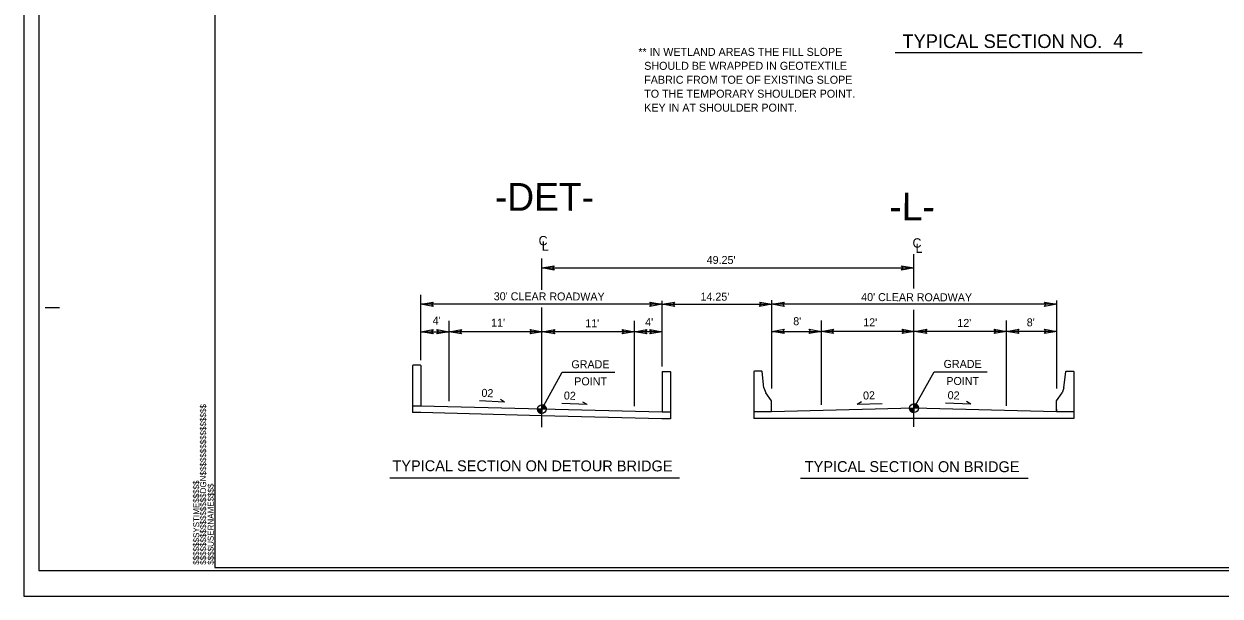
# Model space of a CAD drawing. Extents: x 1497225 to 1499181, y 579958 to 582278.
# Drawn here: x 1497225 to 1498271, y 579958 to 580459 of the extents above; entities that cross this region are included whole.
import ezdxf

# ---------------------------------------------------------------- set-up
doc = ezdxf.new("R2010")
doc.units = 0
for name, color, linetype in [('Old_Level_1', 7, 'Continuous'), ('Old_Level_11', 7, 'Continuous'), ('Old_Level_2', 7, 'Continuous'), ('Old_Level_3', 7, 'Continuous'), ('Prop Dimension Text', 7, 'Continuous'), ('Sheet Cutting Line CELL', 7, 'Continuous'), ('Sheet Plot Border Inside CELL', 7, 'Continuous'), ('Sheet Plot Border Outside CELL', 7, 'Continuous'), ('Sheet Typical CELL', 7, 'Continuous'), ('Typical Text Label CELL', 7, 'Continuous')]:
    doc.layers.add(name, color=color, linetype=linetype)

msp = doc.modelspace()

# ---------------------------------------------------------------- linework, layer by layer
at = {"layer": 'Old_Level_1'}
for p, q in [((1497678.2, 580226), (1497678.2, 580253.2)), ((1498003.6, 580227), (1498003.6, 580257.2)), ((1497678.2, 580245.1), (1498003.6, 580245.1)), ((1497572.3, 580164.3), (1497572.3, 580221.6)), ((1497879.4, 580139.6), (1497879.4, 580216.9)), ((1498128.4, 580139.6), (1498128.4, 580216.5)), ((1497783.5, 580213.3), (1497572.3, 580213.3)), ((1497678.2, 580105.7), (1497678.2, 580210.4)), ((1497783.5, 580158.9), (1497783.5, 580216.2)), ((1497783.5, 580213.3), (1497879.4, 580213.3)), ((1498128.4, 580213.3), (1497879.4, 580213.3)), ((1498003.6, 580106), (1498003.6, 580208.5)), ((1497597.2, 580128.4), (1497597.2, 580198.9)), ((1497759.2, 580124.1), (1497759.2, 580198.9)), ((1497922.6, 580125.2), (1497922.6, 580199.2)), ((1498084.6, 580124.4), (1498084.6, 580199.2)), ((1497572.3, 580189.3), (1497597.2, 580189.3)), ((1497678.7, 580189.3), (1497597.2, 580189.3)), ((1497759.2, 580189.3), (1497678.7, 580189.3)), ((1497783.5, 580189.3), (1497759.2, 580189.3)), ((1497879.4, 580189.6), (1497922.6, 580189.6)), ((1498004.1, 580189.6), (1497922.6, 580189.6)), ((1498084.6, 580189.6), (1498004.1, 580189.6)), ((1498128.4, 580189.6), (1498084.6, 580189.6)), ((1497565.5, 580159.9), (1497565.1, 580159.6)), ((1497565.1, 580159.6), (1497565.1, 580118.5)), ((1497572, 580159.9), (1497565.5, 580159.9)), ((1497572.3, 580159.6), (1497572, 580159.9)), ((1497572.3, 580159.6), (1497572.3, 580124.3)), ((1497678.2, 580121.6), (1497695.9, 580153.9)), ((1497695.9, 580153.9), (1497742, 580153.9)), ((1497783.5, 580154.2), (1497783.8, 580154.5)), ((1497783.5, 580154.2), (1497783.5, 580118.9)), ((1497783.8, 580154.5), (1497790.3, 580154.5)), ((1497790.3, 580154.5), (1497790.7, 580154.2)), ((1497790.7, 580154.2), (1497790.7, 580113.1)), ((1497864, 580154.8), (1497863.6, 580154.4)), ((1497863.6, 580154.4), (1497863.6, 580113.3)), ((1497870.5, 580154.8), (1497864, 580154.8)), ((1497870.9, 580154.4), (1497870.5, 580154.8)), ((1497872.4, 580140.1), (1497870.9, 580154.4)), ((1498003.6, 580122.4), (1498021.3, 580154.2)), ((1498021.3, 580154.2), (1498067.5, 580154.2)), ((1498134.7, 580140.1), (1498136.3, 580154.4)), ((1498136.3, 580154.4), (1498136.6, 580154.8)), ((1498136.6, 580154.8), (1498143.1, 580154.8)), ((1498143.1, 580154.8), (1498143.5, 580154.4)), ((1498143.5, 580154.4), (1498143.5, 580113.3)), ((1497872.4, 580140.1), (1497873.9, 580135.9)), ((1497878.9, 580128.9), (1497873.9, 580135.9)), ((1498128.3, 580128.9), (1498133.2, 580135.9)), ((1498134.7, 580140.1), (1498133.2, 580135.9)), ((1497572.3, 580124.3), (1497565.1, 580124.3)), ((1497678.2, 580121.6), (1497572.3, 580124.3)), ((1497678.2, 580121.6), (1497678.2, 580125.5)), ((1497878.9, 580119.2), (1497878.9, 580128.9)), ((1498003.6, 580122.4), (1497878.9, 580119.2)), ((1497999.8, 580122.4), (1498003.6, 580122.4)), ((1498003.6, 580122.4), (1498003.6, 580126.2)), ((1498007.4, 580122.4), (1498003.6, 580122.4)), ((1498003.6, 580118.6), (1498003.6, 580122.4)), ((1498003.6, 580122.4), (1498003.6, 580118.6)), ((1498128.3, 580119.2), (1498003.6, 580122.4)), ((1498128.3, 580119.2), (1498128.3, 580128.9)), ((1497572.2, 580118.5), (1497565.1, 580118.5)), ((1497678, 580115.8), (1497572.2, 580118.5)), ((1497674.4, 580121.6), (1497678.2, 580121.6)), ((1497783.2, 580113.1), (1497678, 580115.8)), ((1497682, 580121.6), (1497678.2, 580121.6)), ((1497678.2, 580117.8), (1497678.2, 580121.6)), ((1497678.2, 580121.6), (1497678.2, 580117.8)), ((1497783.4, 580118.9), (1497678.2, 580121.6)), ((1497790.7, 580118.9), (1497783.4, 580118.9)), ((1497790.7, 580113.1), (1497783.4, 580113.1)), ((1497878.9, 580119.2), (1497863.6, 580119.2)), ((1498003.6, 580113.3), (1497863.6, 580113.3)), ((1498143.5, 580113.3), (1498003.6, 580113.3)), ((1498128.3, 580121.5), (1498128.3, 580119.2)), ((1498143.5, 580119.2), (1498128.3, 580119.2)), ((1497545.2, 580061.4), (1497798.5, 580061.4)), ((1497904.5, 580061.3), (1498103.6, 580061.3))]:
    msp.add_line(p, q, dxfattribs=at)
for points in [[(1497678.2, 580125.5), (1497678.2, 580125.5), (1497678.2, 580121.6)], [(1497678.2, 580125.5), (1497678.2, 580121.6)], [(1497678.3, 580125.5), (1497678.3, 580121.6)], [(1497678.4, 580125.5), (1497678.4, 580121.6)], [(1497678.5, 580125.4), (1497678.5, 580121.6)], [(1497678.6, 580125.4), (1497678.6, 580121.6)], [(1497678.7, 580125.4), (1497678.7, 580121.6)], [(1497678.8, 580125.4), (1497678.8, 580121.6)], [(1497678.8, 580125.4), (1497678.8, 580121.6)], [(1497678.9, 580125.4), (1497678.9, 580121.6)], [(1497678.9, 580125.4), (1497678.9, 580121.6)], [(1497679, 580125.3), (1497679, 580121.6)], [(1497679.1, 580125.3), (1497679.1, 580121.6)], [(1497679.2, 580125.3), (1497679.2, 580121.6)], [(1497679.3, 580125.3), (1497679.3, 580121.6)], [(1497679.4, 580125.2), (1497679.4, 580121.6)], [(1497679.4, 580125.2), (1497679.4, 580121.6)], [(1497679.5, 580125.2), (1497679.5, 580121.6)], [(1497679.6, 580125.2), (1497679.6, 580121.6)], [(1497679.6, 580125.1), (1497679.6, 580121.6)], [(1497679.7, 580125.1), (1497679.7, 580121.6)], [(1497679.8, 580125), (1497679.8, 580121.6)], [(1497679.9, 580125), (1497679.9, 580121.6)], [(1497680, 580124.9), (1497680, 580121.6)], [(1497680, 580124.9), (1497680, 580121.6)], [(1497680.1, 580124.9), (1497680.1, 580121.6)], [(1497680.2, 580124.9), (1497680.2, 580121.6)], [(1497680.3, 580124.8), (1497680.3, 580121.6)], [(1497680.3, 580124.8), (1497680.3, 580121.6)], [(1497680.4, 580124.7), (1497680.4, 580121.6)], [(1497680.5, 580124.6), (1497680.5, 580121.6)], [(1497680.6, 580124.6), (1497680.6, 580121.6)], [(1497680.6, 580124.5), (1497680.6, 580121.6)], [(1497680.7, 580124.4), (1497680.7, 580121.6)], [(1497680.8, 580124.3), (1497680.8, 580121.6)], [(1497680.9, 580124.3), (1497680.9, 580121.6)], [(1497681, 580124.3), (1497681, 580121.6)], [(1497681, 580124.2), (1497681, 580121.6)], [(1497681.1, 580124.1), (1497681.1, 580121.6)], [(1497681.2, 580123.9), (1497681.2, 580121.6)], [(1497681.2, 580123.8), (1497681.2, 580121.6)], [(1497681.3, 580123.7), (1497681.3, 580121.6)], [(1497681.4, 580123.7), (1497681.4, 580121.6)], [(1497681.5, 580123.5), (1497681.5, 580121.6)], [(1497681.6, 580123.3), (1497681.6, 580121.6)], [(1497681.7, 580123.2), (1497681.7, 580121.6)], [(1497681.7, 580123.1), (1497681.7, 580121.6)], [(1497681.8, 580122.8), (1497681.8, 580121.6)], [(1497681.8, 580122.5), (1497681.8, 580121.6)], [(1497999.8, 580122.4), (1497999.8, 580121.9)], [(1497999.9, 580122.4), (1497999.9, 580121.5)], [(1498000, 580122.4), (1498000, 580121.3)], [(1498000, 580122.4), (1498000, 580121)], [(1498000, 580122.4), (1498000, 580120.8)], [(1498000.1, 580122.4), (1498000.1, 580120.7)], [(1498000.2, 580122.4), (1498000.2, 580120.6)], [(1498000.3, 580122.4), (1498000.3, 580120.4)], [(1498000.4, 580122.4), (1498000.4, 580120.3)], [(1498000.5, 580122.4), (1498000.5, 580120.1)], [(1498000.6, 580122.4), (1498000.6, 580120.1)], [(1498000.6, 580122.4), (1498000.6, 580120)], [(1498000.7, 580122.4), (1498000.7, 580119.9)], [(1498000.7, 580122.4), (1498000.7, 580119.8)], [(1498000.8, 580122.4), (1498000.8, 580119.7)], [(1498000.9, 580122.4), (1498000.9, 580119.6)], [(1498001, 580122.4), (1498001, 580119.5)], [(1498001.1, 580122.4), (1498001.1, 580119.4)], [(1498001.2, 580122.4), (1498001.2, 580119.5)], [(1498001.2, 580122.4), (1498001.2, 580119.4)], [(1498001.3, 580122.4), (1498001.3, 580119.3)], [(1498001.4, 580122.4), (1498001.4, 580119.3)], [(1498001.4, 580122.4), (1498001.4, 580119.2)], [(1498001.5, 580122.4), (1498001.5, 580119.2)], [(1498001.6, 580122.4), (1498001.6, 580119.1)], [(1498001.7, 580122.4), (1498001.7, 580119)], [(1498001.8, 580122.4), (1498001.8, 580119)], [(1498001.8, 580122.4), (1498001.8, 580118.9)], [(1498001.9, 580122.4), (1498001.9, 580118.9)], [(1498002, 580122.4), (1498002, 580118.9)], [(1498002.1, 580122.4), (1498002.1, 580118.9)], [(1498002.1, 580122.4), (1498002.1, 580118.9)], [(1498002.2, 580122.4), (1498002.2, 580118.9)], [(1498002.3, 580122.4), (1498002.3, 580118.8)], [(1498002.4, 580122.4), (1498002.4, 580118.8)], [(1498002.4, 580122.4), (1498002.4, 580118.8)], [(1498002.5, 580122.4), (1498002.5, 580118.7)], [(1498002.6, 580122.4), (1498002.6, 580118.7)], [(1498002.7, 580122.4), (1498002.7, 580118.7)], [(1498002.8, 580122.4), (1498002.8, 580118.7)], [(1498002.8, 580122.4), (1498002.8, 580118.6)], [(1498002.9, 580122.4), (1498002.9, 580118.6)], [(1498003, 580122.4), (1498003, 580118.6)], [(1498003, 580122.4), (1498003, 580118.6)], [(1498003.1, 580122.4), (1498003.1, 580118.6)], [(1498003.2, 580122.4), (1498003.2, 580118.6)], [(1498003.3, 580122.4), (1498003.3, 580118.6)], [(1498003.4, 580122.4), (1498003.4, 580118.6)], [(1498003.5, 580122.4), (1498003.5, 580118.6)], [(1498003.5, 580122.4), (1498003.5, 580118.6), (1498003.5, 580118.6)], [(1498003.6, 580126.2), (1498003.6, 580126.2), (1498003.7, 580122.4)], [(1498003.6, 580126.2), (1498003.7, 580122.4)], [(1498003.7, 580126.2), (1498003.7, 580122.4)], [(1498003.8, 580126.2), (1498003.8, 580122.4)], [(1498003.9, 580126.1), (1498003.9, 580122.4)], [(1498004, 580126.1), (1498004, 580122.4)], [(1498004.1, 580126.1), (1498004.1, 580122.4)], [(1498004.2, 580126.1), (1498004.2, 580122.4)], [(1498004.3, 580126.1), (1498004.3, 580122.4)], [(1498004.3, 580126.1), (1498004.3, 580122.4)], [(1498004.3, 580126.1), (1498004.3, 580122.4)], [(1498004.4, 580126.1), (1498004.4, 580122.4)], [(1498004.5, 580126.1), (1498004.5, 580122.4)], [(1498004.6, 580126.1), (1498004.6, 580122.4)], [(1498004.7, 580126.1), (1498004.7, 580122.4)], [(1498004.8, 580126), (1498004.8, 580122.4)], [(1498004.9, 580126), (1498004.8, 580122.4)], [(1498004.9, 580126), (1498004.9, 580122.4)], [(1498005, 580126), (1498005, 580122.4)], [(1498005, 580125.9), (1498005, 580122.4)], [(1498005.1, 580125.9), (1498005.1, 580122.4)], [(1498005.2, 580125.8), (1498005.2, 580122.4)], [(1498005.3, 580125.8), (1498005.3, 580122.4)], [(1498005.4, 580125.7), (1498005.4, 580122.4)], [(1498005.5, 580125.7), (1498005.5, 580122.4)], [(1498005.5, 580125.6), (1498005.5, 580122.4)], [(1498005.6, 580125.6), (1498005.6, 580122.4)], [(1498005.7, 580125.5), (1498005.7, 580122.4)], [(1498005.7, 580125.5), (1498005.7, 580122.4)], [(1498005.8, 580125.5), (1498005.8, 580122.4)], [(1498005.9, 580125.4), (1498005.9, 580122.4)], [(1498006, 580125.4), (1498006, 580122.4)], [(1498006.1, 580125.3), (1498006.1, 580122.4)], [(1498006.1, 580125.2), (1498006.1, 580122.4)], [(1498006.2, 580125.1), (1498006.2, 580122.4)], [(1498006.3, 580125), (1498006.3, 580122.4)], [(1498006.4, 580125), (1498006.4, 580122.4)], [(1498006.4, 580124.9), (1498006.4, 580122.4)], [(1498006.5, 580124.9), (1498006.5, 580122.4)], [(1498006.6, 580124.7), (1498006.6, 580122.4)], [(1498006.7, 580124.6), (1498006.7, 580122.4)], [(1498006.7, 580124.5), (1498006.7, 580122.4)], [(1498006.8, 580124.4), (1498006.8, 580122.4)], [(1498006.9, 580124.3), (1498006.9, 580122.4)], [(1498007, 580124.1), (1498007, 580122.4)], [(1498007.1, 580124), (1498007.1, 580122.4)], [(1498007.1, 580123.8), (1498007.1, 580122.4)], [(1498007.2, 580123.6), (1498007.2, 580122.4)], [(1498007.3, 580123.3), (1498007.3, 580122.4)], [(1498007.3, 580122.9), (1498007.3, 580122.4)], [(1497674.4, 580121.6), (1497674.4, 580121.2)], [(1497674.5, 580121.6), (1497674.5, 580120.7)], [(1497674.5, 580121.6), (1497674.5, 580120.2)], [(1497674.5, 580121.6), (1497674.5, 580120.5)], [(1497674.6, 580121.6), (1497674.6, 580120.1)], [(1497674.7, 580121.6), (1497674.7, 580119.9)], [(1497674.8, 580121.6), (1497674.8, 580119.8)], [(1497674.9, 580121.6), (1497674.9, 580119.6)], [(1497675, 580121.6), (1497675, 580119.5)], [(1497675.1, 580121.6), (1497675.1, 580119.4)], [(1497675.2, 580121.6), (1497675.2, 580119.3)], [(1497675.2, 580121.6), (1497675.2, 580119.2)], [(1497675.3, 580121.6), (1497675.3, 580119.1)], [(1497675.3, 580121.6), (1497675.3, 580119)], [(1497675.4, 580121.6), (1497675.4, 580118.9)], [(1497675.5, 580121.6), (1497675.5, 580118.9)], [(1497675.6, 580121.6), (1497675.6, 580118.8)], [(1497675.7, 580121.6), (1497675.7, 580118.7)], [(1497675.8, 580121.6), (1497675.8, 580118.7)], [(1497675.8, 580121.6), (1497675.8, 580118.6)], [(1497675.9, 580121.6), (1497675.9, 580118.5)], [(1497676, 580121.6), (1497676, 580118.5)], [(1497676, 580121.6), (1497676, 580118.4)], [(1497676.1, 580121.6), (1497676.1, 580118.4)], [(1497676.2, 580121.6), (1497676.2, 580118.3)], [(1497676.3, 580121.6), (1497676.3, 580118.3)], [(1497676.4, 580121.6), (1497676.4, 580118.3)], [(1497676.4, 580121.6), (1497676.4, 580118.2)], [(1497676.5, 580121.6), (1497676.5, 580118.2)], [(1497676.6, 580121.6), (1497676.6, 580118.2)], [(1497676.7, 580121.6), (1497676.7, 580118.1)], [(1497676.7, 580121.6), (1497676.7, 580118.1)], [(1497676.8, 580121.6), (1497676.8, 580118.1)], [(1497676.9, 580121.6), (1497676.9, 580118)], [(1497677, 580121.6), (1497677, 580118)], [(1497677, 580121.6), (1497677, 580118)], [(1497677.1, 580121.6), (1497677.1, 580117.9)], [(1497677.2, 580121.6), (1497677.2, 580117.9)], [(1497677.3, 580121.6), (1497677.3, 580117.9)], [(1497677.4, 580121.6), (1497677.4, 580117.9)], [(1497677.4, 580121.6), (1497677.4, 580117.8)], [(1497677.5, 580121.6), (1497677.5, 580117.8)], [(1497677.6, 580121.6), (1497677.6, 580117.8)], [(1497677.6, 580121.6), (1497677.6, 580117.8)], [(1497677.7, 580121.6), (1497677.7, 580117.8)], [(1497677.8, 580121.6), (1497677.8, 580117.8)], [(1497677.9, 580121.6), (1497677.9, 580117.8)], [(1497678, 580121.6), (1497678, 580117.8)], [(1497678.1, 580121.6), (1497678.1, 580117.8)], [(1497678.1, 580121.6), (1497678.1, 580117.8), (1497678.1, 580117.8)], [(1497681.9, 580122.1), (1497681.9, 580121.6)]]:
    msp.add_lwpolyline(points, dxfattribs=at)
for centre in [(1497678.2, 580121.6), (1498003.6, 580122.4)]:
    msp.add_circle(centre, 3.82, dxfattribs=at)
for centre, start, end in [((1497678.2, 580121.6), 359.9906, 89.9906), ((1498003.6, 580122.4), 179.9906, 269.9906), ((1498003.6, 580122.4), 359.9906, 89.9906), ((1497678.2, 580121.6), 179.9906, 269.9906)]:
    msp.add_arc(centre, 3.82, start, end, dxfattribs=at)
at = {"layer": 'Old_Level_11'}
for points in [[(1497688.9, 580243.2), (1497678.2, 580245.1), (1497689, 580247), (1497687.6, 580245.1)], [(1497992.8, 580247), (1498003.6, 580245.1), (1497992.8, 580243.2), (1497994.2, 580245.1)], [(1497583, 580211.4), (1497572.3, 580213.3), (1497583.1, 580215.2), (1497581.7, 580213.3)], [(1497772.7, 580215.2), (1497783.5, 580213.3), (1497772.7, 580211.4), (1497774.1, 580213.3)], [(1497794.2, 580211.4), (1497783.5, 580213.3), (1497794.3, 580215.2), (1497792.9, 580213.3)], [(1497868.7, 580215.2), (1497879.4, 580213.3), (1497868.6, 580211.4), (1497870, 580213.3)], [(1497890.2, 580211.4), (1497879.4, 580213.3), (1497890.2, 580215.2), (1497888.9, 580213.3)], [(1498117.7, 580215.2), (1498128.4, 580213.3), (1498117.7, 580211.4), (1498119, 580213.3)], [(1497583, 580187.5), (1497572.3, 580189.3), (1497583.1, 580191.2), (1497581.7, 580189.3)], [(1497586.4, 580191.2), (1497597.2, 580189.3), (1497586.3, 580187.5), (1497587.7, 580189.3)], [(1497607.9, 580187.5), (1497597.2, 580189.3), (1497607.9, 580191.2), (1497606.5, 580189.3)], [(1497667.9, 580191.2), (1497678.7, 580189.3), (1497667.9, 580187.5), (1497669.2, 580189.3)], [(1497689.4, 580187.5), (1497678.7, 580189.3), (1497689.5, 580191.2), (1497688.1, 580189.3)], [(1497748.4, 580191.2), (1497759.2, 580189.3), (1497748.4, 580187.5), (1497749.8, 580189.3)], [(1497769.9, 580187.4), (1497759.2, 580189.3), (1497770, 580191.2), (1497768.6, 580189.3)], [(1497772.7, 580191.2), (1497783.5, 580189.3), (1497772.7, 580187.5), (1497774.1, 580189.3)], [(1497890.2, 580187.7), (1497879.4, 580189.6), (1497890.2, 580191.5), (1497888.9, 580189.6)], [(1497911.8, 580191.5), (1497922.6, 580189.6), (1497911.8, 580187.7), (1497913.1, 580189.6)], [(1497933.3, 580187.7), (1497922.6, 580189.6), (1497933.3, 580191.5), (1497931.9, 580189.6)], [(1497993.4, 580191.5), (1498004.1, 580189.6), (1497993.3, 580187.7), (1497994.6, 580189.6)], [(1498014.8, 580187.7), (1498004.1, 580189.6), (1498014.9, 580191.5), (1498013.5, 580189.6)], [(1498073.8, 580191.5), (1498084.6, 580189.6), (1498073.8, 580187.7), (1498075.2, 580189.6)], [(1498095.3, 580187.7), (1498084.6, 580189.6), (1498095.4, 580191.5), (1498094, 580189.6)], [(1498117.7, 580191.5), (1498128.4, 580189.6), (1498117.7, 580187.7), (1498119, 580189.6)]]:
    msp.add_lwpolyline(points, close=True, dxfattribs=at)
at = {"layer": 'Old_Level_2'}
for p, q in [((1497645.6, 580127.8), (1497623.7, 580128.8)), ((1497645.6, 580127.8), (1497641.9, 580130.1)), ((1497717.7, 580125.5), (1497695.7, 580126.5)), ((1497717.7, 580125.5), (1497714, 580127.8)), ((1497953.9, 580125.8), (1497957.6, 580128.1)), ((1497953.9, 580125.8), (1497975.9, 580126.6)), ((1498053.2, 580125.8), (1498031.3, 580126.8)), ((1498053.2, 580125.8), (1498049.6, 580128.1))]:
    msp.add_line(p, q, dxfattribs=at)
at = {"layer": 'Sheet Cutting Line CELL'}
for p, q in [((1497225.2, 581058), (1497225.2, 579958)), ((1497225.2, 579958), (1498909.2, 579958))]:
    msp.add_line(p, q, dxfattribs=at)
at = {"layer": 'Sheet Plot Border Inside CELL'}
msp.add_lwpolyline([(1498904.7, 581035.6), (1497238.2, 581035.6), (1497238.2, 579980.5), (1498904.7, 579980.5)], close=True, dxfattribs=at)
at = {"layer": 'Sheet Plot Border Outside CELL'}
msp.add_lwpolyline([(1498909.2, 581058), (1497225.2, 581058), (1497225.2, 579958), (1498909.2, 579958)], close=True, dxfattribs=at)
at = {"layer": 'Sheet Typical CELL'}
for p, q in [((1497243.7, 580210.5), (1497256.2, 580210.5)), ((1497392.2, 579983), (1497392.2, 579983)), ((1497392.2, 579983), (1497392.2, 579983)), ((1497392.2, 579983), (1497392.2, 579983)), ((1497392.2, 579983), (1497392.2, 579983)), ((1497392.2, 579983), (1497392.2, 579983)), ((1497392.2, 579983), (1497392.2, 579983))]:
    msp.add_line(p, q, dxfattribs=at)
msp.add_lwpolyline([(1498892.2, 581033), (1497392.2, 581033), (1497392.2, 579983), (1498892.2, 579983)], close=True, dxfattribs=at)
msp.add_lwpolyline([(1497429.7, 579983), (1497429.7, 579983)], dxfattribs=at)
at = {"layer": 'Typical Text Label CELL'}
msp.add_line((1497987.1, 580433.5), (1498203.2, 580433.5), dxfattribs=at)

# ---------------------------------------------------------------- texts
at = {"layer": 'Old_Level_1'}
for s, p in [('** IN WETLAND AREAS THE FILL SLOPE ', (1497762.5, 580430.6)), ('  SHOULD BE WRAPPED IN GEOTEXTILE', (1497762.5, 580418.4)), ('  FABRIC FROM TOE OF EXISTING SLOPE', (1497762.5, 580406.2)), ('  TO THE TEMPORARY SHOULDER POINT.', (1497762.5, 580394)), ('  KEY IN AT SHOULDER POINT.', (1497762.5, 580381.8))]:
    msp.add_text(s, height=7, dxfattribs=at).set_placement(p)
for s, height, rotation, p in [('-DET-', 24.3, 359.9492, (1497637.1, 580295.1)), ('-L-', 24.3, 359.9492, (1497982.1, 580286.7)), ("49.25'", 7, 359.8458, (1497822.3, 580248.6)), ("30' CLEAR ROADWAY", 7, 359.8458, (1497636.1, 580216.8)), ("14.25'", 7, 359.8458, (1497816.9, 580216.5)), ("40' CLEAR ROADWAY", 7, 359.8458, (1497957.4, 580216.1)), ("4'", 7, 359.8458, (1497582.7, 580195.6)), ("11'", 7, 359.8458, (1497633.8, 580193.7)), ("11'", 7, 359.8458, (1497716.1, 580193.2)), ("4'", 7, 359.8458, (1497768.5, 580194.2)), ("8'", 7, 359.8458, (1497898, 580195)), ("12'", 7, 359.8458, (1497959.2, 580194)), ("12'", 7, 359.8458, (1498041.5, 580193.5)), ("8'", 7, 359.8458, (1498102.2, 580194)), ('02', 7, 357.3937, (1497625.2, 580132.4)), ('02', 7, 357.3937, (1497697.3, 580130.1)), ('02', 7, 2.2942, (1497959.2, 580129.9)), ('02', 7, 357.3937, (1498032.9, 580130.4)), ('TYPICAL SECTION ON DETOUR BRIDGE ', 9.5, 359.9492, (1497547.5, 580067.3)), ('TYPICAL SECTION ON BRIDGE ', 9.5, 359.9492, (1497908.1, 580066.6))]:
    msp.add_text(s, height=height, rotation=rotation, dxfattribs=at).set_placement(p)
at = {"layer": 'Old_Level_3'}
for s, p in [('C', (1497675.3, 580264.9)), ('C', (1498002.3, 580262.9)), ('L', (1497678, 580260.3)), ('L', (1498005, 580258.3))]:
    msp.add_text(s, height=8.15, rotation=359.8458, dxfattribs=at).set_placement(p)
at = {"layer": 'Prop Dimension Text'}
for s, p in [('GRADE', (1497704, 580157.3)), ('GRADE', (1498029.5, 580157.6)), ('POINT', (1497706.5, 580142.4)), ('POINT', (1498031.9, 580142.7))]:
    msp.add_text(s, height=7, rotation=0.0001, dxfattribs=at).set_placement(p)
at = {"layer": 'Sheet Typical CELL'}
for s, p in [('$$$$$$$$$$$$$$$$DGN$$$$$$$$$$$$$$$$', (1497384.6, 579985.4)), ('$$$$$$SYSTIME$$$$$', (1497378.5, 579985.4)), ('$$$$USERNAME$$$$', (1497391.2, 579985.4))]:
    msp.add_text(s, height=5.25, rotation=90, dxfattribs=at).set_placement(p)
at = {"layer": 'Typical Text Label CELL'}
for s, height, p in [('TYPICAL SECTION NO.  ', 11.936, (1497993.5, 580437.5)), ('4', 11.9, (1498178, 580437.7))]:
    msp.add_text(s, height=height, dxfattribs=at).set_placement(p)

doc.saveas('drawing.dxf')
